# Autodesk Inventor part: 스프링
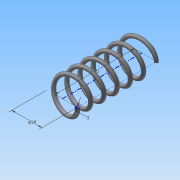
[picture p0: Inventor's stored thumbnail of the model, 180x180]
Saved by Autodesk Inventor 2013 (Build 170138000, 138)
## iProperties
Created: 2016-04
Part Number: 스프링
Material: Generic
Document SubType Name: Modeling
Designer: Administrator
Density: 1 g/cm^3
Author: Administrator
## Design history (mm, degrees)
sketch "스케치1"
  geometry: L1 (0, 0)-(8, 0); L2 (8, 0)-(8, 42); L3 (8, 42)-(0, 42); L4 (0, 42)-(0, 0); C1 r 1 at (8, 0)
  constraints: 8 end point, 2 parallel, 1 centre point, 1 coincident, 1 horizontal, 1 perpendicular
  dimensions: "d0" = 42 distance of L3.end L1.start (derived); "d1" = 16 diameter of L2 L4; "d2" = 2 diameter of C1
feature "코일1" sketch "스케치1" pitch "d3" = 10; turns "d5" = 6; dims "d4" = 42 (= d0), "d6" = 0, angle "d7" = 90 deg, angle "d8" = 90 deg, "d9" = 0, "d10" = 0
sketch "스케치2"
  geometry: L1 (42, 24.186)-(0, 24.186); L2 (0, 24.186)-(0, -24.186); L3 (0, -24.186)-(42, -24.186); L4 (42, -24.186)-(42, 24.186); 4 further points
  constraints: 8 end point, 3 coincident, 2 midpoint, 2 parallel, 1 horizontal, 1 perpendicular
  dimensions: "d11" = 48.37288 distance of L1.end L2.end
extrude "돌출1" sketch "스케치2" stored distance "d13" = 40; taper "d14" = 0 deg
node "솔리드1"
